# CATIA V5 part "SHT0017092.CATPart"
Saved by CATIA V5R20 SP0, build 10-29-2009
Part number: 零件1
Bounding box of the stored display mesh (mm): x -515.232 to -263.855, y -808.498 to -649.499, z 111.046 to 161.092
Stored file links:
  F:\福田A6\1-数据\6-冻结数据\第三批\SHT0017092 A6司机滑轨解锁手柄\SHT0017092.CATPart
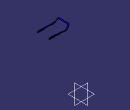
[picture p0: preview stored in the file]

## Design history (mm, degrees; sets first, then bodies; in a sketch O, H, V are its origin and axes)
Set1
  Plane1: type 1Curve, Element1 edge [face of Solid1 | face of Solid1]
  Line1: type PtDir, RefPoint {point type Center, Curve edge [face of Split1 | face of Solid1]}, Direction Line4, Start 0, End 80
  Line2: type PtDir, RefPoint {point type Center, Curve DatumCurve1}, Direction (0, 1, 0), Start 15, End -30
  DatumCurve1
  Line3: type PtPt, FirstPoint vertex of Line1, SecondPoint vertex of Line2
  Corner1: Element1 Line2, Element2 Line3, Radius 15
  Corner2: Element1 Corner1, Element2 {inverselocal InverseElem Line1}, Radius 15
  Plane2: type Offset, RefPlane face of Solid1, Offset 69.5, reversed
  Rotate1: ToTransfor Body2, Axis DatumCurve2, Angle -5
  DatumCurve2
  Line4: stored without definition
  Point1: type Center, Curve edge [face of Mirror1 | face of Mirror1]
  Point2: type Center, Curve edge [face of Rib1 | face of Rib1]
  Line5: type PtPt, FirstPoint Point2, SecondPoint Point1
  Point3: type Center, Curve edge [face of Mirror1 | face of Mirror1]
  Point4: type Center, Curve edge [face of Rib1 | face of Rib1]
  Line6: type PtPt, FirstPoint Point3, SecondPoint Point4
  Point5: type OnCurve, Support Line6, Ratio 0.5
  Point6: type OnCurve, Support Line5, Ratio 0.5
  Line7: type PtPt, FirstPoint Point6, SecondPoint Point5
  Plane3: type 2Lines, Element1 Line6, Element2 Line7
Body1 (main body)
Body2 "Brep With Voids"
  Solid1: solid without history
  Split1: SplitPlane Plane1
  Sketch1 on face of Split1, origin (-393.172, 0, 0), H (0, -1, 0), V (0, 0, 1)
    projected arc E1 centre (654.4988, 122.4) radius 5 from (659.4988, 122.4) to (649.4988, 122.4) ccw from edge [face of Split1 | face of Solid1]
    projected arc E2 centre (654.4988, 122.4) radius 5 from (649.4988, 122.4) to (659.4988, 122.4) ccw from edge [face of Split1 | face of Solid1]
    projected arc E3 centre (654.4988, 122.4) radius 3.5 from (657.9988, 122.4) to (650.9988, 122.4) ccw from edge [face of Solid1 | face of Split1]
    projected arc E4 centre (654.4988, 122.4) radius 3.5 from (650.9988, 122.4) to (657.9988, 122.4) ccw from edge [face of Solid1 | face of Split1]
  Rib1: profile Sketch1, centre curve Corner2
  Thickness1: Thickness 50, Face face of Rib1
  Split2: SplitPlane Plane2
  Mirror1: of the body so far, about Plane2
